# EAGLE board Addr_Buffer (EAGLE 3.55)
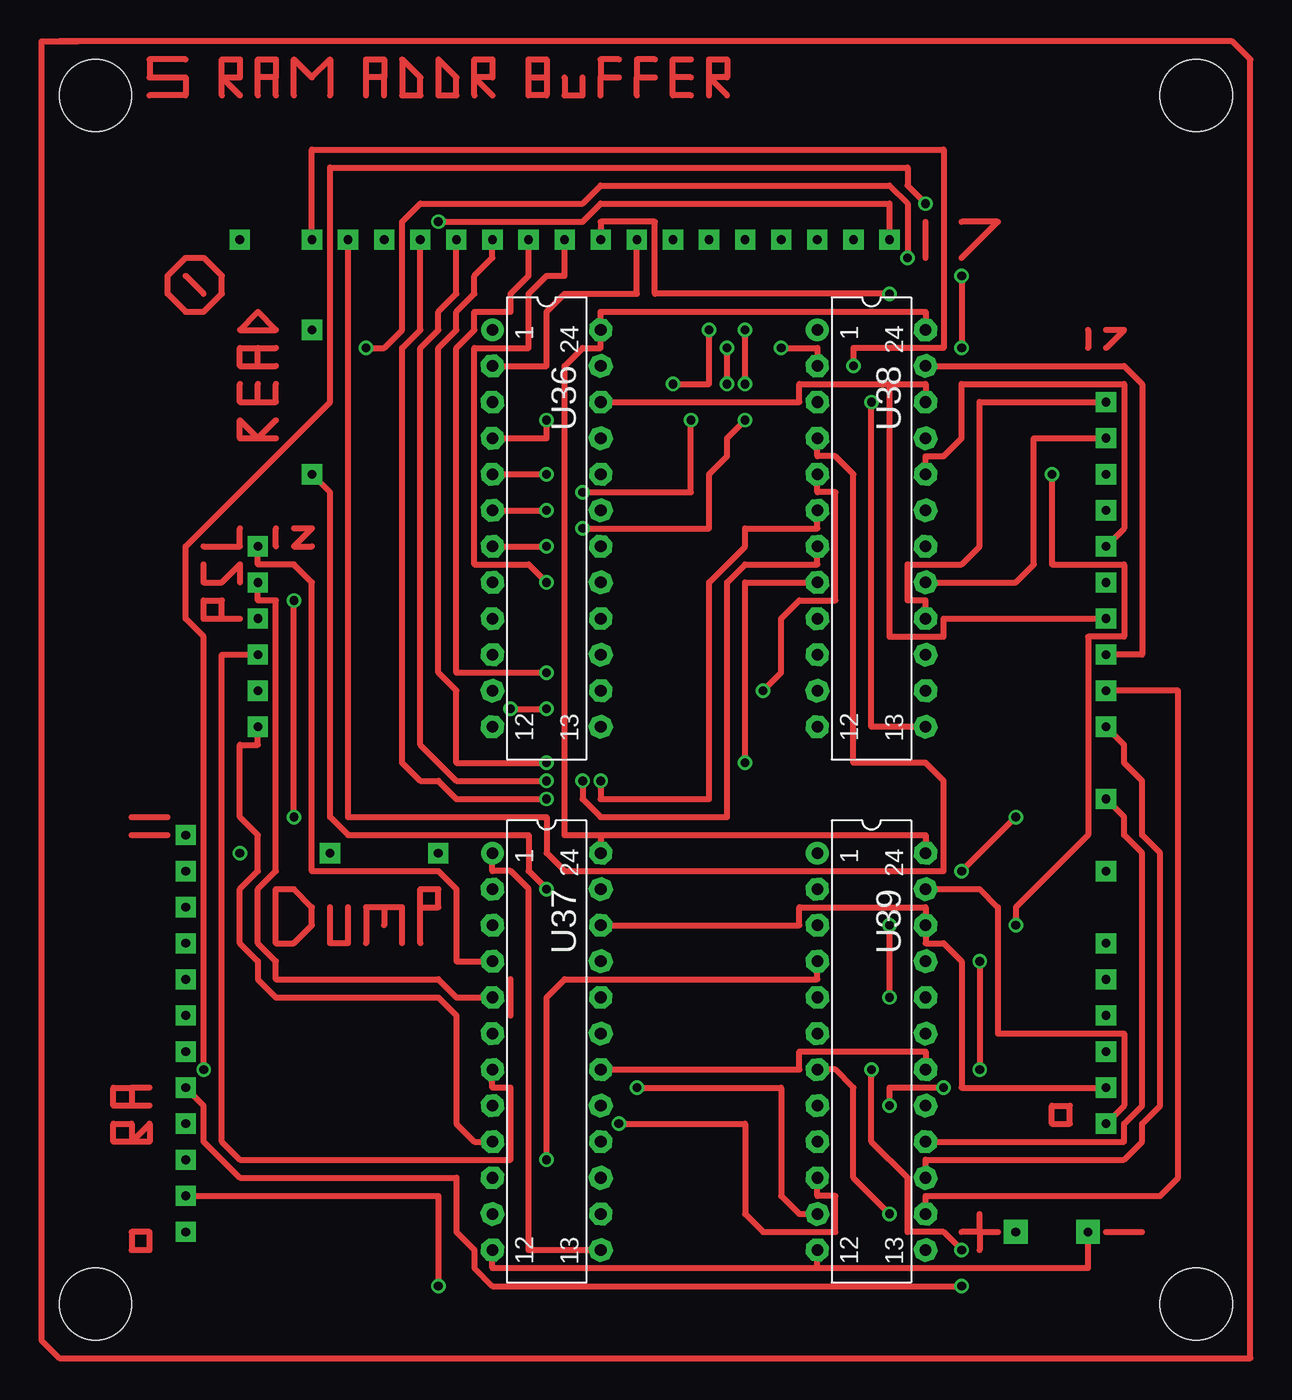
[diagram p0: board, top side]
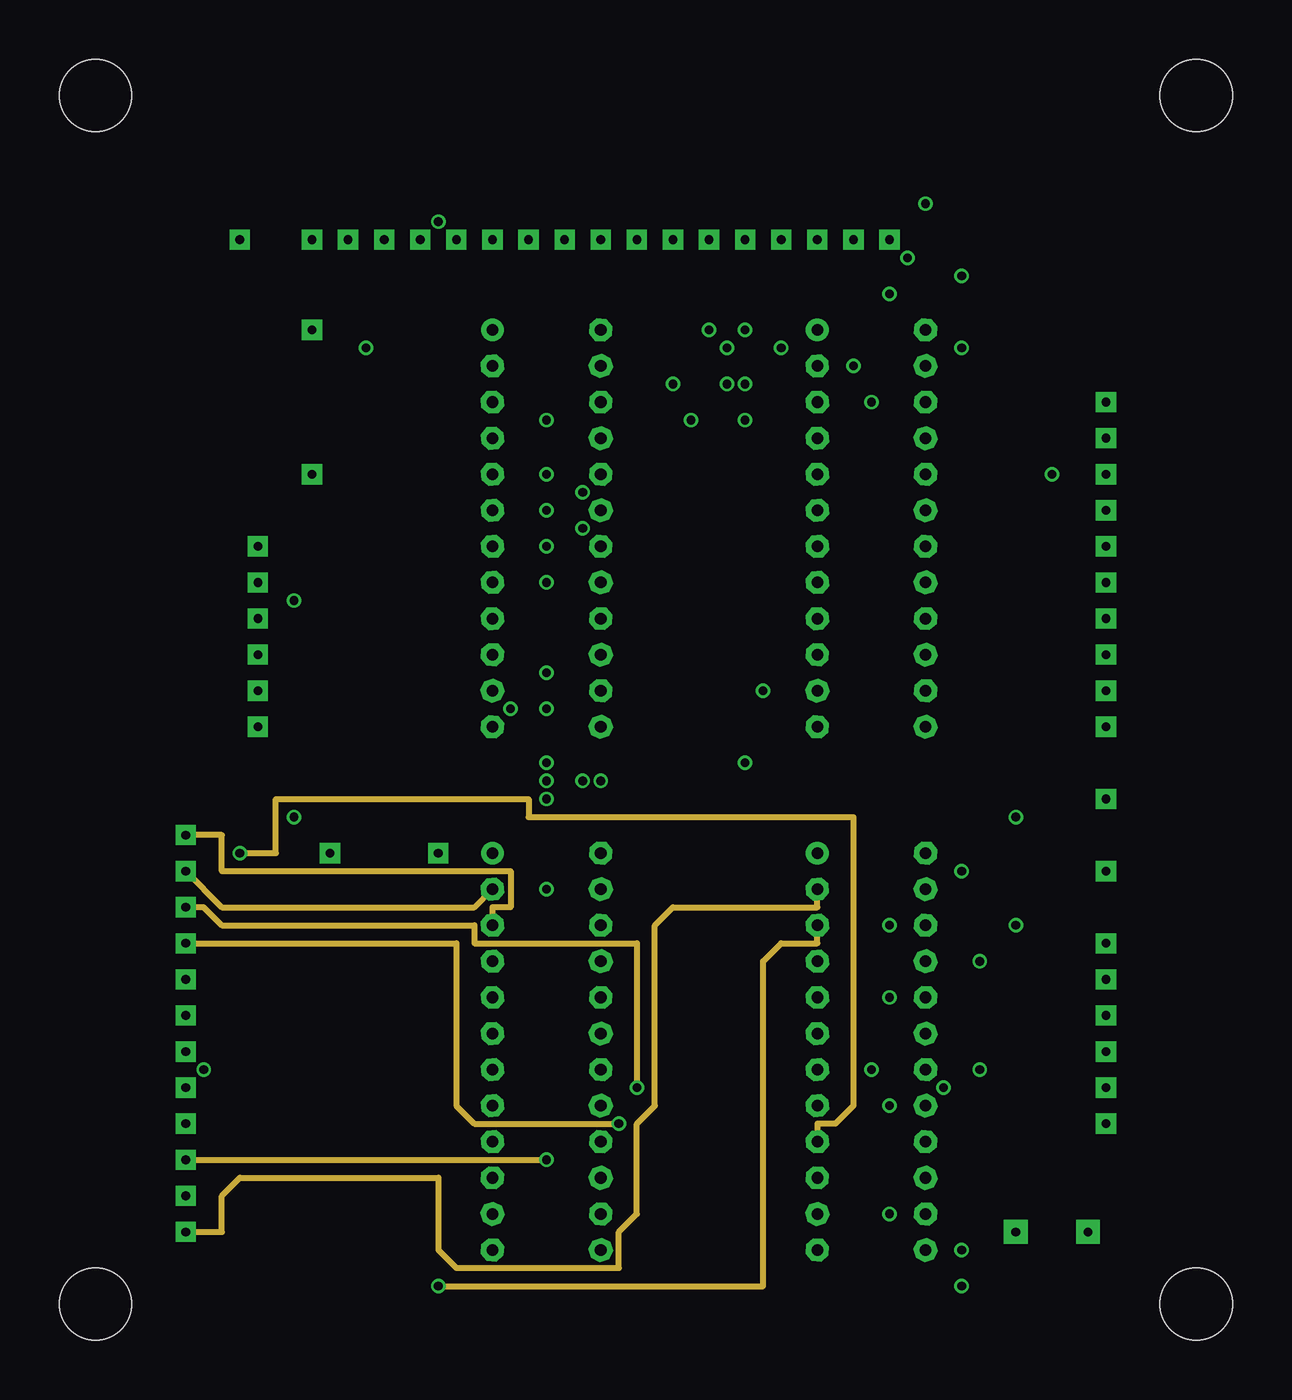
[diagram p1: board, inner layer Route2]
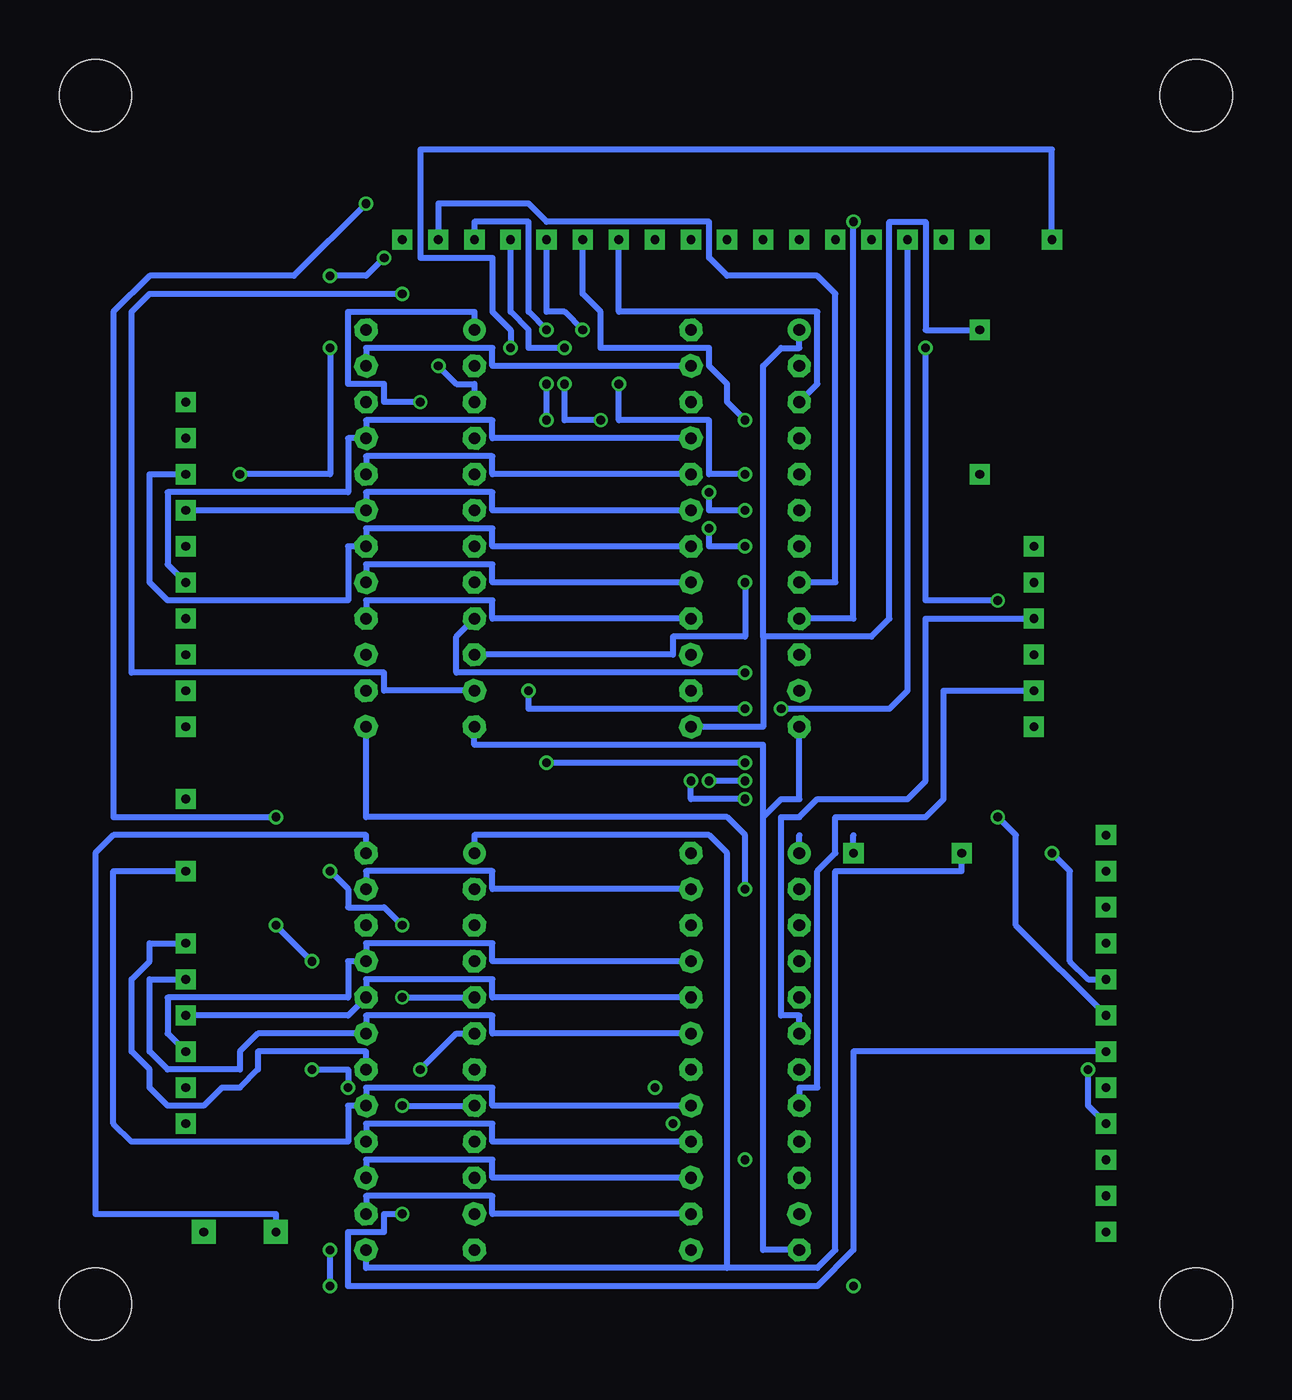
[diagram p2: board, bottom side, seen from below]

No outline drawn. Coordinates in mm, seen from the top.
Copper layers used: Top, Route2, Bottom
Holes 5.08 mm at -20.32,116.84 57.15,116.84 -20.32,31.75 57.15,31.75

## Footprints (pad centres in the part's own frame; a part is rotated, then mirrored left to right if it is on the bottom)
L24-3 = drill 0.813 pad 1.6 round:  -13.97,-3.81 | drill 0.813 pad 1.6 octagon:  -11.43,-3.81;  -8.89,-3.81;  -6.35,-3.81;  -3.81,-3.81;  -1.27,-3.81;  1.27,-3.81;  3.81,-3.81;  6.35,-3.81;  8.89,-3.81;  11.43,-3.81;  13.97,-3.81;  13.97,3.81;  11.43,3.81;  8.89,3.81;  6.35,3.81;  3.81,3.81;  1.27,3.81;  -1.27,3.81;  -3.81,3.81;  -6.35,3.81;  -8.89,3.81;  -11.43,3.81;  -13.97,3.81

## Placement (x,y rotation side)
U36  74F827  [L24-3]  11.43,86.36 270 top
U37  74F827  [L24-3]  11.43,49.53 270 top
U38  74F827  [L24-3]  34.29,86.36 270 top
U39  74F827  [L24-3]  34.29,49.53 270 top

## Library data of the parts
U36-U39 = memhitch

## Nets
S$1: U36. U38.
S$2: U36. U38.
S$3: U36. U38.
S$4: U36. U38.
S$5: U36. U38.
S$6: U36. U38.
S$7: U36. U38.
S$8: U36. U38.
S$9: U37. U39.
S$10: U37. U39.
S$11: U37. U39.
S$12: U37. U39.
S$13: U37. U39.
S$14: U37. U39.
S$15: U37. U39.
S$16: U37. U39.
S$17: U37. U39.
S$18: U37. U39.
S$19: U36.
S$20: U38.
S$21: U37.
S$22: U39.
S$23: U36. U37. U38. U39.
S$24: U36. U37. U38. U39.
S$27: U38.
S$28: U38.
S$29: U38.
S$30: U38.
S$31: U38.
S$32: U38.
S$33: U38.
S$34: U38.
S$35: U38.
S$36: U38.
S$37: U36.
S$38: U36.
S$39: U36.
S$40: U36.
S$41: U36.
S$42: U36.
S$43: U36.
S$44: U36.
S$61: U37.
S$62: U37.
S$63: U37.
S$65: U37.
S$66: U37.
S$67: U37.
S$73: U37.
S$74: U37.
S$75: U39.
S$76: U39.
S$77: U39.
S$78: U39.
S$79: U39.
S$80: U39.
S$81: U39.
S$82: U39.
S$83: U39.
S$84: U39.

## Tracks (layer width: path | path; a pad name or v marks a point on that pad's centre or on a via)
S$1  (via drill 0.61 pad 1.42)
  Top 0.406: v50.8,95.25 41.91,95.25 41.91,85.09 40.64,83.82 36.83,83.82 36.83,81.28 38.1,81.28 38.1,80.01
  Bottom 0.406: 15.24,80.01 29.21,80.01 29.21,81.28 38.1,81.28 38.1,80.01
S$2  (via drill 0.61 pad 1.42)
  Top 0.406: v50.8,92.71 45.72,92.71 45.72,83.82 44.45,82.55 38.1,82.55
  Bottom 0.406: 15.24,82.55 29.21,82.55 29.21,83.82 38.1,83.82 38.1,82.55
S$3  (via drill 0.61 pad 1.42)
  Bottom 0.406: 15.24,85.09 29.21,85.09 29.21,86.36 38.1,86.36 38.1,85.09 39.37,85.09 39.37,81.28 52.07,81.28 53.34,82.55 53.34,90.17 v50.8,90.17
S$4  (via drill 0.61 pad 1.42)
  Bottom 0.406: 15.24,87.63 29.21,87.63 29.21,88.9 38.1,88.9 38.1,87.63 v50.8,87.63
S$5  (via drill 0.61 pad 1.42)
  Top 0.406: v50.8,85.09 52.07,86.36 52.07,96.52 40.64,96.52 40.64,92.71 39.37,91.44 38.1,91.44 38.1,90.17
  Bottom 0.406: 15.24,90.17 29.21,90.17 29.21,91.44 38.1,91.44 38.1,90.17
S$6  (via drill 0.61 pad 1.42)
  Bottom 0.406: 15.24,92.71 29.21,92.71 29.21,93.98 38.1,93.98 38.1,92.71 39.37,92.71 39.37,88.9 52.07,88.9 52.07,83.82 v50.8,82.55
S$7  (via drill 0.61 pad 1.42)
  Top 0.406: 15.24,95.25 29.21,95.25 29.21,96.52 35.56,96.52 | 35.56,96.52 38.1,96.52 38.1,95.25 | v50.8,80.01 39.37,80.01 39.37,78.74 35.56,78.74 35.56,96.52
S$8  (via drill 0.61 pad 1.42)
  Top 0.406: v50.8,77.47 53.34,77.47 53.34,96.52 52.07,97.79 38.1,97.79
  Bottom 0.406: 15.24,97.79 29.21,97.79 29.21,99.06 38.1,99.06 38.1,97.79
S$9  (via drill 0.61 pad 1.42)
  Top 0.406: v50.8,74.93 55.88,74.93 55.88,40.64 54.61,39.37 38.1,39.37 38.1,38.1
  Bottom 0.406: 15.24,38.1 29.21,38.1 29.21,39.37 38.1,39.37 38.1,38.1
S$10  (via drill 0.61 pad 1.42)
  Top 0.406: v50.8,72.39 52.07,71.12 52.07,69.85 53.34,68.58 53.34,64.77 54.61,63.5 54.61,45.72 53.34,44.45 53.34,43.18 52.07,41.91 38.1,41.91 38.1,40.64
  Bottom 0.406: 15.24,40.64 29.21,40.64 29.21,41.91 38.1,41.91 38.1,40.64
S$11  (via drill 0.61 pad 1.42)
  Top 0.406: v50.8,67.31 52.07,66.04 52.07,64.77 53.34,63.5 53.34,45.72 52.07,44.45 52.07,43.18 38.1,43.18
  Bottom 0.406: 15.24,43.18 29.21,43.18 29.21,44.45 38.1,44.45 38.1,43.18
S$12  (via drill 0.61 pad 1.42)
  Bottom 0.406: 15.24,45.72 29.21,45.72 29.21,46.99 38.1,46.99 38.1,45.72 39.37,45.72 39.37,43.18 54.61,43.18 55.88,44.45 55.88,62.23 v50.8,62.23
S$13  (via drill 0.61 pad 1.42)
  Top 0.406: 15.24,48.26 29.21,48.26 29.21,49.53 38.1,49.53 38.1,48.26
  Bottom 0.406: v50.8,57.15 53.34,57.15 53.34,55.88 54.61,54.61 54.61,49.53 53.34,48.26 53.34,46.99 52.07,45.72 49.53,45.72 48.26,46.99 46.99,46.99 45.72,48.26 45.72,49.53 38.1,49.53 38.1,48.26
S$14  (via drill 0.61 pad 1.42)
  Bottom 0.406: 15.24,50.8 29.21,50.8 29.21,52.07 38.1,52.07 38.1,50.8 45.72,50.8 46.99,49.53 46.99,48.26 52.07,48.26 53.34,49.53 53.34,54.61 v50.8,54.61
S$15  (via drill 0.61 pad 1.42)
  Bottom 0.406: 15.24,53.34 29.21,53.34 29.21,54.61 38.1,54.61 38.1,53.34 39.37,52.07 v50.8,52.07
S$16  (via drill 0.61 pad 1.42)
  Bottom 0.406: 15.24,55.88 29.21,55.88 29.21,57.15 38.1,57.15 38.1,55.88 39.37,55.88 39.37,53.34 52.07,53.34 52.07,50.8 v50.8,49.53
S$17  (via drill 0.61 pad 1.42)
  Top 0.406: 15.24,58.42 29.21,58.42 29.21,59.69 38.1,59.69 38.1,58.42 38.1,57.15 39.37,57.15 40.64,55.88 40.64,46.99 v50.8,46.99
S$18  (via drill 0.61 pad 1.42)
  Top 0.406: v50.8,44.45 52.07,45.72 52.07,50.8 43.18,50.8 43.18,59.69 41.91,60.96 38.1,60.96
  Bottom 0.406: 15.24,60.96 29.21,60.96 29.21,62.23 38.1,62.23 38.1,60.96
S$19  (via drill 0.61 pad 1.42)
  Bottom 0.406: 15.24,72.39 10.16,72.39 10.16,78.74 | 10.16,78.74 10.16,97.79 8.89,99.06 7.62,99.06 7.62,100.33 | v-5.08,100.33 -1.27,100.33 -1.27,107.95 1.27,107.95 1.27,80.01 2.54,78.74 10.16,78.74
S$20  (via drill 0.61 pad 1.02, 0.61 pad 1.42)
  Top 0.406: 38.1,72.39 34.29,72.39 v34.29,95.25 | v-5.08,90.17 -3.81,88.9 -3.81,66.04 -2.54,64.77 10.16,64.77 10.16,62.23 v11.43,60.96
  Bottom 0.406: v34.29,95.25 36.83,95.25 36.83,96.52 39.37,96.52 39.37,101.6 30.48,101.6 30.48,100.33 | v11.43,60.96 11.43,64.77 12.7,66.04 38.1,66.04 38.1,72.39
S$21
  Top 0.406: 7.62,63.5 7.62,62.23 8.89,62.23 10.16,60.96 10.16,35.56 15.24,35.56
  Bottom 0.406: 7.62,63.5 7.62,64.77
S$22  (via drill 0.61 pad 1.42)
  Bottom 0.406: 38.1,35.56 38.1,34.29 12.7,34.29 | 12.7,34.29 12.7,63.5 13.97,64.77 30.48,64.77 30.48,63.5 | v-3.81,63.5 -3.81,62.23 5.08,62.23 5.08,35.56 6.35,34.29 12.7,34.29
S$23  (via drill 0.61 pad 1.68)
  Top 0.406: 15.24,64.77 U37. | 15.24,64.77 12.7,64.77 12.7,97.79 13.97,99.06 15.24,99.06 U36. 15.24,101.6 38.1,101.6 U38. | U39. 38.1,64.77 15.24,64.77
  Bottom 0.406: v44.45,36.83 44.45,38.1 57.15,38.1 57.15,63.5 55.88,64.77 38.1,64.77 U39.
S$24  (via drill 0.61 pad 1.68)
  Top 0.406: 30.48,34.29 30.48,35.56 | 30.48,34.29 49.53,34.29 v49.53,36.83 | 30.48,34.29 7.62,34.29 7.62,35.56
  Bottom 0.406: 7.62,35.56 10.16,35.56 10.16,66.04 | 10.16,66.04 8.89,67.31 7.62,67.31 7.62,72.39 | 30.48,72.39 30.48,71.12 10.16,71.12 10.16,66.04
S$25
  Top 0.406: 41.91,36.83 41.91,35.56 | 41.91,36.83 41.91,38.1 | 41.91,36.83 40.64,36.83 | 41.91,36.83 43.18,36.83
S$26
  Top 0.406: 50.8,36.83 53.34,36.83
S$27  (via drill 0.61 pad 1.02, 0.61 pad 1.42)
  Top 0.406: v27.94,99.06 30.48,99.06 30.48,97.79
  Bottom 0.406: v-10.16,106.68 -10.16,113.03 34.29,113.03 34.29,105.41 29.21,105.41 29.21,101.6 27.94,100.33 v27.94,99.06
S$28  (via drill 0.61 pad 1.02, 0.61 pad 1.42)
  Top 0.406: v-5.08,106.68 -5.08,113.03 39.37,113.03 39.37,99.06 33.02,99.06 v33.02,97.79
  Bottom 0.406: v33.02,97.79 31.75,96.52 30.48,96.52 30.48,95.25
S$29  (via drill 0.61 pad 1.42)
  Top 0.406: v-2.54,106.68 -2.54,66.04 11.43,66.04 11.43,63.5 12.7,62.23 39.37,62.23 39.37,68.58 38.1,69.85 33.02,69.85 33.02,90.17 31.75,91.44 30.48,91.44 30.48,92.71
S$30  (via drill 0.61 pad 1.02, 0.61 pad 1.42)
  Top 0.406: v8.89,73.66 v11.43,73.66 | v26.67,74.93 27.94,76.2 27.94,80.01 29.21,81.28 31.75,81.28 31.75,88.9 30.48,88.9 30.48,90.17
  Bottom 0.406: v0,106.68 0,74.93 1.27,73.66 v8.89,73.66 | v11.43,73.66 26.67,73.66 v26.67,74.93
S$31  (via drill 0.61 pad 1.02, 0.61 pad 1.42)
  Top 0.406: v2.54,106.68 2.54,100.33 1.27,99.06 1.27,69.85 2.54,68.58 3.81,68.58 5.08,67.31 v11.43,67.31 | v15.24,68.58 15.24,67.31 22.86,67.31 22.86,82.55 25.4,85.09 25.4,86.36 30.48,86.36 30.48,87.63
  Bottom 0.406: v11.43,67.31 15.24,67.31 v15.24,68.58
S$32  (via drill 0.61 pad 1.02, 0.61 pad 1.42)
  Top 0.406: v5.08,106.68 5.08,102.87 3.81,101.6 3.81,100.33 2.54,99.06 2.54,71.12 5.08,68.58 v11.43,68.58 | v13.97,68.58 13.97,67.31 15.24,66.04 24.13,66.04 24.13,82.55 25.4,83.82 30.48,83.82 30.48,85.09
  Bottom 0.406: v11.43,68.58 v13.97,68.58
S$33  (via drill 0.61 pad 1.02, 0.61 pad 1.42)
  Top 0.406: 30.48,82.55 25.4,82.55 v25.4,69.85 | v11.43,69.85 5.08,69.85 5.08,74.93 3.81,76.2 3.81,99.06 5.08,100.33 5.08,101.6 6.35,102.87 6.35,104.14 7.62,105.41 v7.62,106.68
  Bottom 0.406: v11.43,69.85 v25.4,69.85
S$34  (via drill 0.61 pad 1.02, 0.61 pad 1.42)
  Top 0.406: v11.43,76.2 5.08,76.2 5.08,99.06 6.35,100.33 6.35,101.6 8.89,101.6 8.89,102.87 10.16,104.14 v10.16,106.68
  Bottom 0.406: 30.48,80.01 31.75,78.74 31.75,76.2 v11.43,76.2
S$35  (via drill 0.61 pad 1.02, 0.61 pad 1.42)
  Top 0.406: v11.43,82.55 10.16,83.82 6.35,83.82 6.35,99.06 10.16,99.06 10.16,102.87 11.43,104.14 12.7,104.14 v12.7,106.68
  Bottom 0.406: 30.48,77.47 16.51,77.47 16.51,78.74 11.43,78.74 v11.43,82.55
S$36  (via drill 0.61 pad 1.02, 0.61 pad 1.42)
  Top 0.406: v35.56,102.87 19.05,102.87 19.05,107.95 15.24,107.95 v15.24,106.68
  Bottom 0.406: 30.48,74.93 36.83,74.93 36.83,76.2 54.61,76.2 54.61,101.6 53.34,102.87 v35.56,102.87
S$37  (via drill 0.61 pad 1.42)
  Top 0.406: 7.62,97.79 11.43,97.79 11.43,101.6 12.7,102.87 17.78,102.87 v17.78,106.68
S$38  (via drill 0.61 pad 1.42)
  Bottom 0.406: 7.62,95.25 6.35,96.52 6.35,101.6 20.32,101.6 v20.32,106.68
S$39  (via drill 0.61 pad 1.02, 0.61 pad 1.42)
  Top 0.406: 7.62,92.71 11.43,92.71 v11.43,93.98
  Bottom 0.406: v11.43,93.98 12.7,95.25 12.7,96.52 13.97,97.79 13.97,99.06 21.59,99.06 21.59,101.6 22.86,102.87 v22.86,106.68
S$40  (via drill 0.61 pad 1.02, 0.61 pad 1.42)
  Top 0.406: 7.62,90.17 v11.43,90.17 | v20.32,96.52 22.86,96.52 v22.86,100.33
  Bottom 0.406: v11.43,90.17 13.97,90.17 13.97,93.98 20.32,93.98 v20.32,96.52 | v22.86,100.33 24.13,101.6 25.4,101.6 v25.4,106.68
S$41  (via drill 0.61 pad 1.02, 0.61 pad 1.42)
  Top 0.406: 7.62,87.63 v11.43,87.63 | v13.97,88.9 21.59,88.9 v21.59,93.98 | v24.13,96.52 v24.13,99.06
  Bottom 0.406: v11.43,87.63 13.97,87.63 v13.97,88.9 | v21.59,93.98 24.13,93.98 v24.13,96.52 | v24.13,99.06 26.67,99.06 26.67,100.33 27.94,101.6 v27.94,106.68
S$42  (via drill 0.61 pad 1.02, 0.61 pad 1.42)
  Top 0.406: 7.62,85.09 v11.43,85.09 | v13.97,86.36 22.86,86.36 22.86,90.17 24.13,91.44 24.13,92.71 v25.4,93.98 | v25.4,96.52 v25.4,100.33
  Bottom 0.406: v11.43,85.09 13.97,85.09 v13.97,86.36 | v25.4,93.98 v25.4,96.52 | v25.4,100.33 26.67,101.6 26.67,107.95 30.48,107.95 v30.48,106.68
S$43  (via drill 0.61 pad 1.42)
  Bottom 0.406: 7.62,82.55 5.08,82.55 5.08,102.87 6.35,104.14 12.7,104.14 13.97,105.41 13.97,107.95 25.4,107.95 26.67,109.22 33.02,109.22 v33.02,106.68
S$44  (via drill 0.61 pad 1.02, 0.61 pad 1.42)
  Top 0.406: v3.81,107.95 13.97,107.95 15.24,109.22 35.56,109.22 v35.56,106.68
  Bottom 0.406: 7.62,80.01 3.81,80.01 v3.81,107.95
S$45
  Top 0.406: -13.97,105.41 -12.7,105.41 -11.43,104.14 -11.43,102.87 -12.7,101.6 -13.97,101.6 -15.24,102.87 -15.24,104.14 -13.97,105.41
S$46
  Top 0.406: -12.7,102.87 -13.97,104.14
S$47
  Top 0.406: 38.1,105.41 38.1,107.95
S$48
  Top 0.406: 40.64,107.95 43.18,107.95 40.64,105.41
S$49
  Top 0.406: 46.99,44.45 46.99,45.72 48.26,45.72 48.26,44.45 46.99,44.45
S$50
  Top 0.406: 49.53,100.33 49.53,99.06
S$51
  Top 0.406: 50.8,100.33 52.07,100.33 50.8,99.06
S$52
  Top 0.406: -7.62,57.15 -7.62,60.96 -6.35,60.96 -5.08,59.69 -5.08,58.42 -6.35,57.15 -7.62,57.15
S$53
  Top 0.406: -3.81,59.69 -3.81,57.15 -2.54,57.15 -2.54,59.69
S$54
  Top 0.406: -1.27,57.15 -1.27,59.69 0,59.69 | 0,59.69 0,58.42 | 0,59.69 1.27,59.69 1.27,57.15
S$55
  Top 0.406: 2.54,57.15 2.54,59.69 | 2.54,59.69 2.54,60.96 3.81,60.96 3.81,59.69 2.54,59.69
S$56
  Top 0.406: -8.89,92.71 -7.62,92.71 | -8.89,92.71 -10.16,92.71 -10.16,93.98 -8.89,92.71 | -8.89,92.71 -7.62,93.98
S$57
  Top 0.406: -7.62,96.52 -7.62,95.25 -8.89,95.25 | -8.89,95.25 -8.89,96.52 | -8.89,95.25 -10.16,95.25 -10.16,96.52
S$58
  Top 0.406: -8.89,97.79 -7.62,97.79 | -8.89,97.79 -10.16,97.79 -10.16,99.06 -8.89,99.06 | -8.89,99.06 -7.62,99.06 | -8.89,97.79 -8.89,99.06
S$59
  Top 0.406: -10.16,100.33 -7.62,100.33 -8.89,101.6 -10.16,100.33
S$60
  Top 0.406: 8.89,52.07 8.89,54.61
S$61  (via drill 0.61 pad 1.42)
  Top 0.406: 7.62,55.88 5.08,55.88 5.08,60.96 3.81,62.23 -5.08,62.23 -5.08,82.55 -6.35,83.82 -8.89,83.82 v-8.89,85.09
S$62  (via drill 0.61 pad 1.42)
  Bottom 0.406: 7.62,50.8 7.62,52.07 8.89,52.07 8.89,66.04 7.62,66.04 6.35,67.31 0,67.31 -1.27,68.58 -1.27,80.01 v-8.89,80.01
S$63  (via drill 0.61 pad 1.42)
  Top 0.406: 7.62,53.34 5.08,53.34 3.81,54.61 -7.62,54.61 -7.62,55.88 -8.89,57.15 -8.89,60.96 -7.62,62.23 -7.62,81.28 -8.89,81.28 v-8.89,82.55
S$64  (via drill 0.61 pad 1.42)
  Bottom 0.406: v3.81,63.5 3.81,64.77
S$65  (via drill 0.61 pad 1.42)
  Top 0.406: v-8.89,77.47 -11.43,77.47 -11.43,43.18 -10.16,41.91 8.89,41.91 8.89,46.99 7.62,46.99 7.62,48.26
S$66  (via drill 0.61 pad 1.42)
  Bottom 0.406: v-8.89,74.93 -2.54,74.93 -2.54,67.31 -1.27,66.04 5.08,66.04 5.08,63.5 6.35,62.23 6.35,46.99 7.62,46.99 7.62,45.72
S$67  (via drill 0.61 pad 1.42)
  Top 0.406: 7.62,43.18 6.35,43.18 5.08,44.45 5.08,52.07 3.81,53.34 -7.62,53.34 -8.89,54.61 -8.89,55.88 -10.16,57.15 -10.16,60.96 -8.89,62.23 -8.89,64.77 -10.16,66.04 -10.16,71.12 -8.89,71.12 v-8.89,72.39
S$68
  Top 0.406: -7.62,85.09 -7.62,86.36
S$69
  Top 0.406: -6.35,86.36 -5.08,86.36 -6.35,85.09 -5.08,85.09
S$70
  Top 0.406: -11.43,80.01 -10.16,80.01 | -11.43,80.01 -12.7,80.01 -12.7,81.28 -11.43,81.28 -11.43,80.01
S$71
  Top 0.406: -12.7,83.82 -12.7,82.55 -11.43,82.55 -10.16,83.82 -10.16,82.55
S$72
  Top 0.406: -12.7,85.09 -10.16,85.09 -10.16,86.36
S$73  (via drill 0.61 pad 1.42)
  Route2 0.406: v-13.97,64.77 -11.43,64.77 -11.43,62.23 8.89,62.23 8.89,59.69 7.62,59.69 7.62,58.42
S$74  (via drill 0.61 pad 1.42)
  Route2 0.406: v-13.97,62.23 -11.43,59.69 6.35,59.69 7.62,60.96
S$75  (via drill 0.61 pad 1.02, 0.61 pad 1.42)
  Top 0.406: v17.78,46.99 27.94,46.99 27.94,39.37 29.21,38.1 30.48,38.1
  Route2 0.406: v-13.97,59.69 -12.7,59.69 -11.43,58.42 6.35,58.42 6.35,57.15 17.78,57.15 v17.78,46.99
S$76  (via drill 0.61 pad 1.02, 0.61 pad 1.42)
  Top 0.406: v16.51,44.45 25.4,44.45 25.4,38.1 26.67,36.83 31.75,36.83 31.75,39.37 30.48,39.37 30.48,40.64
  Route2 0.406: v-13.97,57.15 5.08,57.15 5.08,45.72 6.35,44.45 v16.51,44.45
S$77  (via drill 0.61 pad 1.02, 0.61 pad 1.42)
  Route2 0.406: v-10.16,63.5 -7.62,63.5 -7.62,67.31 10.16,67.31 10.16,66.04 33.02,66.04 33.02,45.72 31.75,44.45 30.48,44.45 30.48,43.18
  Bottom 0.406: v-13.97,54.61 -12.7,54.61 -11.43,55.88 -11.43,62.23 v-10.16,63.5
S$78  (via drill 0.61 pad 1.02, 0.61 pad 1.42)
  Top 0.406: v-6.35,66.04 v-6.35,81.28 | v-1.27,99.06 0,99.06 1.27,100.33 1.27,107.95 2.54,109.22 13.97,109.22 15.24,110.49 35.56,110.49 36.83,109.22 v36.83,105.41 | v40.64,104.14 v40.64,99.06 | v46.99,90.17 46.99,83.82 52.07,83.82 52.07,78.74 49.53,78.74 49.53,64.77 44.45,59.69 v44.45,58.42 | v41.91,55.88 v41.91,48.26 | v39.37,46.99 35.56,46.99 v35.56,45.72
  Bottom 0.406: v-13.97,52.07 -7.62,58.42 -7.62,64.77 v-6.35,66.04 | v-6.35,81.28 -1.27,81.28 v-1.27,99.06 | v36.83,105.41 38.1,104.14 v40.64,104.14 | v40.64,99.06 40.64,90.17 v46.99,90.17 | v44.45,58.42 v41.91,55.88 | v41.91,48.26 39.37,48.26 v39.37,46.99 | v35.56,45.72 30.48,45.72
S$79  (via drill 0.61 pad 1.02, 0.61 pad 1.42)
  Top 0.406: v35.56,38.1 33.02,40.64 33.02,46.99 31.75,48.26 30.48,48.26
  Bottom 0.406: v-13.97,49.53 3.81,49.53 3.81,35.56 6.35,33.02 39.37,33.02 39.37,36.83 36.83,36.83 36.83,38.1 v35.56,38.1
S$80  (via drill 0.61 pad 1.02, 0.61 pad 1.42)
  Top 0.406: v-13.97,46.99 -12.7,45.72 -12.7,43.18 -10.16,40.64 5.08,40.64 5.08,36.83 6.35,35.56 6.35,34.29 7.62,33.02 v40.64,33.02 | v40.64,35.56 39.37,36.83 36.83,36.83 36.83,40.64 34.29,43.18 v34.29,48.26
  Bottom 0.406: v40.64,33.02 v40.64,35.56 | v34.29,48.26 31.75,50.8 30.48,50.8
S$81  (via drill 0.61 pad 1.02, 0.61 pad 1.42)
  Top 0.406: v-12.7,48.26 -12.7,78.74 -13.97,80.01 -13.97,85.09 -3.81,95.25 -3.81,111.76 36.83,111.76 36.83,110.49 v38.1,109.22 | v44.45,66.04 v40.64,62.23 | v35.56,58.42 v35.56,53.34
  Bottom 0.406: v-13.97,44.45 -12.7,45.72 v-12.7,48.26 | v38.1,109.22 43.18,104.14 53.34,104.14 55.88,101.6 55.88,66.04 v44.45,66.04 | v40.64,62.23 39.37,60.96 39.37,59.69 36.83,59.69 v35.56,58.42 | v35.56,53.34 30.48,53.34
S$82  (via drill 0.61 pad 1.02, 0.61 pad 1.42)
  Top 0.406: v11.43,41.91 11.43,53.34 12.7,54.61 30.48,54.61 30.48,55.88
  Route2 0.406: v-13.97,41.91 v11.43,41.91
S$83  (via drill 0.61 pad 1.02, 0.61 pad 1.42)
  Top 0.406: v-13.97,39.37 3.81,39.37 v3.81,33.02
  Route2 0.406: v3.81,33.02 26.67,33.02 26.67,55.88 27.94,57.15 30.48,57.15 30.48,58.42
S$84  (via drill 0.61 pad 1.42)
  Route2 0.406: v-13.97,36.83 -11.43,36.83 -11.43,39.37 -10.16,40.64 3.81,40.64 3.81,35.56 5.08,34.29 16.51,34.29 16.51,36.83 17.78,38.1 17.78,44.45 19.05,45.72 19.05,58.42 20.32,59.69 30.48,59.69 30.48,60.96
S$85
  Top 0.406: -17.78,64.77 -15.24,64.77
S$86
  Top 0.406: -17.78,66.04 -15.24,66.04
S$87
  Top 0.406: -17.78,36.83 -17.78,35.56 -16.51,35.56 -16.51,36.83 -17.78,36.83
S$88
  Top 0.406: -17.78,43.18 -16.51,43.18 -16.51,44.45 -17.78,43.18 | -17.78,43.18 -19.05,43.18 -19.05,44.45 -17.78,44.45 -17.78,43.18
S$89
  Top 0.406: -16.51,45.72 -17.78,45.72 | -17.78,45.72 -19.05,45.72 -19.05,46.99 -17.78,46.99 | -16.51,46.99 -17.78,46.99 | -17.78,46.99 -17.78,45.72
S$90
  Top 0.406: -21.59,120.65 59.69,120.65 60.96,119.38 60.96,27.94 -22.86,27.94 -24.13,29.21 -24.13,120.65 -21.59,120.65 | -21.59,120.65 -22.86,120.65
S$91
  Top 0.406: -13.97,119.38 -16.51,119.38 -16.51,118.11 -13.97,118.11 -13.97,116.84 -16.51,116.84
S$92
  Top 0.406: -11.43,116.84 -11.43,118.11 | -11.43,118.11 -11.43,119.38 -10.16,119.38 -10.16,118.11 -11.43,118.11 | -11.43,118.11 -10.16,116.84
S$93
  Top 0.406: -8.89,116.84 -8.89,118.11 | -8.89,118.11 -8.89,119.38 -7.62,119.38 -7.62,118.11 | -7.62,116.84 -7.62,118.11 | -7.62,118.11 -8.89,118.11
S$94
  Top 0.406: -6.35,116.84 -6.35,119.38 -5.08,118.11 -3.81,119.38 -3.81,116.84
S$95
  Top 0.406: -1.27,116.84 -1.27,118.11 | -1.27,118.11 -1.27,119.38 0,119.38 0,118.11 | 0,116.84 0,118.11 | 0,118.11 -1.27,118.11
S$96
  Top 0.406: 1.27,119.38 1.27,116.84 2.54,116.84 2.54,118.11 1.27,119.38
S$97
  Top 0.406: 3.81,119.38 3.81,116.84 5.08,116.84 5.08,118.11 3.81,119.38
S$98
  Top 0.406: 6.35,116.84 6.35,118.11 | 6.35,118.11 6.35,119.38 7.62,119.38 7.62,118.11 6.35,118.11 | 6.35,118.11 7.62,116.84
S$99
  Top 0.406: 10.16,118.11 10.16,116.84 11.43,116.84 11.43,118.11 | 10.16,118.11 10.16,119.38 11.43,119.38 11.43,118.11 | 10.16,118.11 11.43,118.11
S$100
  Top 0.406: 12.7,118.11 12.7,116.84 13.97,116.84 13.97,118.11
S$101
  Top 0.406: 15.24,116.84 15.24,118.11 | 16.51,119.38 15.24,119.38 15.24,118.11 | 15.24,118.11 16.51,118.11
S$102
  Top 0.406: 17.78,116.84 17.78,118.11 | 19.05,119.38 17.78,119.38 17.78,118.11 | 17.78,118.11 19.05,118.11
S$103
  Top 0.406: 21.59,116.84 20.32,116.84 20.32,118.11 | 21.59,118.11 20.32,118.11 | 20.32,118.11 20.32,119.38 21.59,119.38
S$104
  Top 0.406: 22.86,116.84 22.86,118.11 | 22.86,118.11 22.86,119.38 24.13,119.38 24.13,118.11 22.86,118.11 | 22.86,118.11 24.13,116.84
